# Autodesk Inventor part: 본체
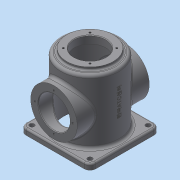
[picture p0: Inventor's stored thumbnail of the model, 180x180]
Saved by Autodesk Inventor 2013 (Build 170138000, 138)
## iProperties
Created: 2015-10
Part Number: 본체
Material: 일반
Document SubType Name: Modeling
Designer: ST4
Density: 1 g/cm^3
Author: ST4
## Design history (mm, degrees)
sketch "스케치1"
  geometry: L1 (-50, 60)-(50, 60); L2 (60, 50)-(60, -50); L3 (50, -60)-(-50, -60); L4 (-60, -50)-(-60, 50); A1 r 10 centre (-50, 50) between (-50, 60) and (-60, 50); A2 r 10 centre (50, 50) between (60, 50) and (50, 60); A3 r 10 centre (50, -50) between (50, -60) and (60, -50); A4 r 10 centre (-50, -50) between (-60, -50) and (-50, -60); 4 further points
  constraints: 8 end point, 8 point on circle, 8 tangent, 6 point on line, 4 centre point, 3 equal radius, 2 parallel, 1 horizontal, 1 perpendicular
  dimensions: "d0" = 120 distance of point (60, -60) point (-60, -60); "d2" = 120 distance of point (-60, -60) point (-60, 60); "d3" = 60 distance from line of point (0, 0) L3; "d4" = 60 distance from line of point (0, 0) L4; "d5" = 10 radius of A1
extrude "돌출1" new body sketch "스케치1" distance "d6" = 10; taper "d7" = 0 deg
sketch "스케치2"
  geometry: L1 (60, 10)-(60, 0) reference; L2 (60, 0)-(-60, 0) reference; L3 (-60, 0)-(-60, 10) reference; L4 (-60, 10)-(60, 10) reference; L5 (0, 0)-(0, 129.105); L6 (-28, 125)-(-40, 125); L7 (-40, 125)-(-40, 123); L8 (-43, 120)-(-45, 120); L9 (-50, 115)-(-50, 10); L10 (-27, 124)-(-27, 112); L11 (-27, 112)-(-42, 112); L12 (-45, 109)-(-45, 10); L13 (-28, 125)-(-27, 124); A1 r 5 centre (-45, 115) between (-45, 120) and (-50, 115); A2 r 3 centre (-43, 123) between (-43, 120) and (-40, 123); A3 r 3 centre (-42, 109) between (-42, 112) and (-45, 109); 2 further points
  constraints: 18 end point, 6 perpendicular, 6 point on circle, 6 point on line, 6 tangent, 3 centre point, 2 parallel
  dimensions: "d10" = 100 diameter of point (-50, 120) L5; "d11" = 80 diameter of L6.end L5; "d12" = 125 distance between parallel lines of L6 L2; "d14" = 110 distance between parallel lines of L8 L4; "d15" = 5 radius of A1; "d16" = 3 radius of A2; "d17" = 54 diameter of L10 L5; "d18" = 13 distance between parallel lines of L11 L6; "d19" = 90 diameter of L12 L5; "d20" = 1 distance of L6.start point (-27, 125); "d21" = 1 distance of L10.start point (-27, 125) (= d20); "d22" = 3 radius of A3
revolve "회전1" sketch "스케치2" stored, may be unused: angle "d23" = 90 deg
sketch "스케치3"
  geometry: C1 r 45 at (0, 0); 1 further point
  constraints: 1 centre point, 1 coincident
  dimensions: "d24" = 90 diameter of C1
extrude "돌출2" cut sketch "스케치3" distance "d26" = 10; taper "d27" = 0 deg
node "작업 평면1"
chamfer "모따기3" distance "d47" = 1; stored, may be unused: second distance "d48" = 2, angle "d49" = 45 deg
fillet "모깎기3" dims "d50" = 5
fillet "모깎기4" dims "d51" = 3
sketch "스케치6"
  geometry: C1 r 55 at (0, 0) reference; C2 r 4 at (50, -50); C3 r 4 at (50, 50); C4 r 4 at (-50, 50); C5 r 4 at (-50, -50); A1 r 7 centre (50, -50) between (50, -57) and (57, -50) reference
  constraints: 4 centre point, 1 coincident, 9 other
  dimensions: "d52" = 8 diameter of C2; "d56" = 360 deg dimension on C1.centre C2.centre (derived)
extrude "돌출5" cut sketch "스케치6" distance "d58" = 10; taper "d59" = 0 deg
sketch "스케치7" dims "d61" = 65
  geometry: L1 (0, 0)-(0, 28); L2 (0, 0)-(-28.284, 28.284); 3 further points
  constraints: 4 end point, 1 coincident, 1 point on line, 1 vertical, 1 vertical alignment, 6 other
  dimensions: "d60" = 45 deg angle of L1 L2
hole "구멍1" sketch "스케치7" at (-22.981, 22.981) diameter "d63" = 3.242; stored, may be unused: countersink angle "d67" = 90 deg, drill point angle "d69" = 118 deg; dims "d64" = 8, "d65" = 4, "d66" = 2, "d68" = 10
node "작업 평면3"
  node "작업 평면2"
sketch "스케치10"
  geometry: L1 (-5.17, -18.655)-(-5.17, 33.655); L2 (-5.17, 33.655)-(5.17, 33.655); L3 (5.17, 33.655)-(5.17, -18.655); L4 (5.17, -18.655)-(-5.17, -18.655); L5 (0, 33.655)-(0, -18.655); L6 (5.17, 7.5)-(-5.17, 7.5); L7 (-46, -62.5)-(46, -62.5) reference; 1 further point
  constraints: 4 end point, 4 midpoint, 2 other
  dimensions: "d98" = 0 distance from line of point (0, -62.5) L5; "d99" = 70 distance from line of L6.end L7
extrude "돌출6" join sketch "스케치10" stored distance "d100" = 10; taper "d101" = 0 deg
node "작업 평면4"
sketch "스케치11"
  geometry: L1 (50, 0)-(-50, 0) reference; C1 r 40 at (0, 60); 1 further point
  constraints: 1 centre point
  dimensions: "d103" = 80 diameter of C1; "d105" = 0 horizontal distance of point (0, 0) C1.centre; "d106" = 60 distance from line of L1 C1.centre
extrude "돌출7" join sketch "스케치11" stored distance "d107" = 10; taper "d108" = 0 deg
sketch "스케치12"
  geometry: C1 r 40 at (0, 0) reference; C2 r 27 at (0, 0); 1 further point
  constraints: 1 centre point, 1 coincident
  dimensions: "d109" = 54 diameter of C2
extrude "돌출8" cut sketch "스케치12" stored distance "d111" = 10; taper "d112" = 0 deg
chamfer "모따기4" distance "d113" = 1; stored, may be unused: second distance "d114" = 2, angle "d115" = 45 deg
fillet "모깎기5" dims "d116" = 5
fillet "모깎기6" dims "d117" = 3
chamfer "모따기5" distance "d118" = 1; stored, may be unused: second distance "d119" = 2, angle "d120" = 45 deg
sketch "스케치13"
  geometry: C1 r 40 at (0, 0) reference; 2 further points
  dimensions: "d121" = 0 vertical distance of point (32.5, 0) C1.centre; "d122" = 32.5 distance of C1.centre point (32.5, 0)
hole "구멍4" sketch "스케치13" at (32.5, 0) diameter "d123" = 3.242; stored, may be unused: countersink angle "d127" = 90 deg, drill point angle "d129" = 118 deg; dims "d124" = 8, "d125" = 4, "d126" = 2, "d128" = 10
node "솔리드1"
pattern_circular "원형 패턴1" dims angle "d71" = 360 deg
mirror "대칭2"
mirror "대칭3"
pattern_circular "원형 패턴4" dims angle "d131" = 360 deg
mirror "대칭4"
node "절단 모서리 투영1"
other parameters: "d28" = -62.5, "d97" = 0.5, "d102" = 62
